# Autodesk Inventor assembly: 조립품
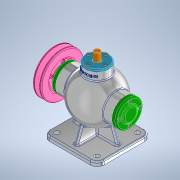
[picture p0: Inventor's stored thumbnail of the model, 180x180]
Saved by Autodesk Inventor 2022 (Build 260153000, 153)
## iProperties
Created: 2024-04
Part Number: 조립품
Document SubType Name: Assembly
Designer: user
Author: user
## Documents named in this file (16)
- C:\Users\user\Desktop\740406V1007\조립품.iam
- C:\Users\user\Desktop\740406V1007\본체.ipt
- C:\Users\user\Desktop\740406V1007\뒤커버.ipt
- C:\Users\user\Desktop\740406V1007\앞커버.ipt
- C:\Users\user\Desktop\740406V1007\상부커버.ipt
- C:\Users\user\Desktop\740406V1007\베어링- 6202.ipt
- KS B 2023 - 6202 - 15 x 35 x 11 - 7.8.ipt
- C:\Users\user\Desktop\740406V1007\칼라.ipt
- C:\Users\user\Desktop\740406V1007\편심축.ipt
- C:\Users\user\Desktop\740406V1007\키 4 x 4 x 12.ipt
- C:\Users\user\Desktop\740406V1007\오일실 15 30 7.ipt
- C:\Users\user\Desktop\740406V1007\V-벨트풀리.ipt
- C:\Users\user\Desktop\740406V1007\너트 M8.ipt
- C:\Users\user\Desktop\740406V1007\볼트 M4 x 16.ipt
- C:\Users\user\Desktop\740406V1007\볼트 M4 x 12.ipt
- C:\Users\user\Desktop\740406V1007\슬라이드.ipt
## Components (15 placed, 4 different names)
1. KS B 2023 - 6202 - 15 x 35 x 11 - 7.8:1
2. KS B 2023 - 6202 - 15 x 35 x 11 - 7.8:2
3. V-벨트풀리:1
4. ISO 4762 M4 x 16:1
5. ISO 4762 M4 x 16:2
6. ISO 4762 M4 x 16:3
7. ISO 4762 M4 x 16:4
8. ISO 4762 M4 x 16:5
9. ISO 4762 M4 x 16:6
10. ISO 4762 M4 x 16:7
11. ISO 4762 M4 x 16:8
12. KS B 1021 - 에 따름 ISO 1207 - 미터 A  M 4 x 12:1
13. KS B 1021 - 에 따름 ISO 1207 - 미터 A  M 4 x 12:2
14. KS B 1021 - 에 따름 ISO 1207 - 미터 A  M 4 x 12:3
15. KS B 1021 - 에 따름 ISO 1207 - 미터 A  M 4 x 12:4
